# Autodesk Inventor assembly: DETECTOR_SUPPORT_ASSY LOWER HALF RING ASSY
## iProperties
Shininess: 64.0
Length Units: 11272
Angle Units: 11279
Time Units: 11290
Mass Units: 11286
Length Display Precision: 3
Angle Display Precision: 2
Compacted: True
Part Number: DETECTOR_SUPPORT_ASSY LOWER HALF RING ASSY
Document SubType Name: Assembly
Created: 2004-08
Designer: John Blackburn
Manufacturer: Standard
Standards Organization: Custom
Density: 0.0
Volumn: 0.0
Area: 0.0
PropertySet Name: Model Information
Control State: 0
Master: False
Checked Out: False
Author: John Blackburn
